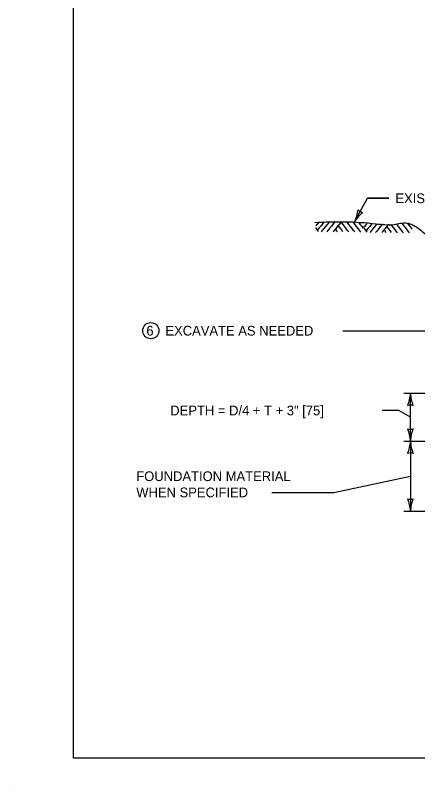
# Model space of a CAD drawing. Extents: x 49991.4 to 50021, y 49987.6 to 50011.4.
# Drawn here: x 49999.024 to 50001.509, y 49987.599 to 49992.388 of the extents above; entities that cross this region are included whole.
import ezdxf

# ---------------------------------------------------------------- set-up
doc = ezdxf.new("R2010")
doc.units = 0
for name, color, linetype in [('Level 1', 7, 'Continuous'), ('Level 2', 7, 'Continuous'), ('Level 3', 7, 'Continuous')]:
    doc.layers.add(name, color=color, linetype=linetype)

msp = doc.modelspace()

# ---------------------------------------------------------------- linework, layer by layer
at = {"layer": 'Level 1'}
msp.add_line((49999.0245, 49987.5988), (49999.0245, 49987.5988), dxfattribs=at)
msp.add_lwpolyline([(49999.3835, 49998.9992), (50016.7501, 49998.9992), (50016.7501, 49987.7988), (49999.3835, 49987.7988)], close=True, dxfattribs=at)
for points in [[(50000.8978, 49991.0536), (50000.8918, 49991.0618), (50000.89, 49991.0614), (50000.8904, 49991.0629), (50000.8821, 49991.0736), (50000.8827, 49991.0757), (50000.8806, 49991.0759), (50000.8801, 49991.0766)], [(50000.8988, 49991.1098), (50000.8906, 49991.1002), (50000.8914, 49991.0986), (50000.8898, 49991.0986), (50000.8813, 49991.0881), (50000.8802, 49991.0882)], [(50000.932, 49991.1125), (50000.922, 49991.1009), (50000.9228, 49991.0993), (50000.9212, 49991.0993), (50000.9127, 49991.0888), (50000.9106, 49991.0889), (50000.9108, 49991.0868), (50000.902, 49991.0763), (50000.902, 49991.0742), (50000.9001, 49991.0736), (50000.8932, 49991.0649)], [(50000.9648, 49991.1137), (50000.9521, 49991.0989), (50000.9529, 49991.0973), (50000.9513, 49991.0973), (50000.9428, 49991.0869), (50000.9406, 49991.0869), (50000.9409, 49991.0849), (50000.9321, 49991.0743), (50000.9321, 49991.0722), (50000.9302, 49991.0716), (50000.9218, 49991.0611), (50000.9198, 49991.061), (50000.9202, 49991.059), (50000.9141, 49991.0519)], [(50000.9985, 49991.1131), (50000.9862, 49991.0986), (50000.9869, 49991.097), (50000.9853, 49991.0971), (50000.9768, 49991.0866), (50000.9747, 49991.0866), (50000.9749, 49991.0846), (50000.9661, 49991.074), (50000.9661, 49991.072), (50000.9642, 49991.0713), (50000.9559, 49991.0609), (50000.9539, 49991.0607), (50000.9542, 49991.0587), (50000.9482, 49991.0516)], [(50001.0388, 49991.1139), (50001.0261, 49991.0991), (50001.0268, 49991.0974), (50001.0252, 49991.0975), (50001.0167, 49991.087), (50001.0146, 49991.087), (50001.0148, 49991.085), (50001.0061, 49991.0744), (50001.006, 49991.0724), (50001.0041, 49991.0717), (50000.9958, 49991.0613), (50000.9937, 49991.0612), (50000.9941, 49991.0591), (50000.9881, 49991.052)], [(50001.0484, 49991.052), (50001.0389, 49991.0644), (50001.037, 49991.0649), (50001.0368, 49991.0668), (50001.0284, 49991.0774), (50001.0288, 49991.0793), (50001.0267, 49991.0794), (50001.0189, 49991.0899)], [(50001.0839, 49991.0504), (50001.0786, 49991.0577), (50001.0769, 49991.0573), (50001.0773, 49991.0588), (50001.069, 49991.0695), (50001.0695, 49991.0715), (50001.0675, 49991.0718), (50001.0591, 49991.0827), (50001.0572, 49991.0832), (50001.057, 49991.0852), (50001.0487, 49991.0957), (50001.049, 49991.0977), (50001.047, 49991.0978), (50001.0375, 49991.1104)], [(50001.1207, 49991.0505), (50001.1145, 49991.0588), (50001.1128, 49991.0584), (50001.1132, 49991.06), (50001.1049, 49991.0706), (50001.1054, 49991.0727), (50001.1034, 49991.0729), (50001.095, 49991.0839), (50001.0931, 49991.0844), (50001.0929, 49991.0863), (50001.0846, 49991.0969), (50001.0849, 49991.0989), (50001.0829, 49991.099), (50001.0725, 49991.1128)], [(50001.1596, 49991.0491), (50001.1534, 49991.0574), (50001.1517, 49991.057), (50001.1521, 49991.0585), (50001.1438, 49991.0692), (50001.1443, 49991.0713), (50001.1423, 49991.0715), (50001.134, 49991.0824), (50001.132, 49991.0829), (50001.1318, 49991.0849), (50001.1235, 49991.0954), (50001.1238, 49991.0974), (50001.1218, 49991.0975), (50001.1126, 49991.1098)], [(50001.1759, 49991.0718), (50001.1681, 49991.082), (50001.1662, 49991.0825), (50001.166, 49991.0845), (50001.1577, 49991.095), (50001.158, 49991.097), (50001.1559, 49991.0971), (50001.1482, 49991.1075)], [(50001.1787, 49991.0833), (50001.1776, 49991.0833), (50001.1778, 49991.0813), (50001.1746, 49991.0773)], [(50001.1983, 49991.1033), (50001.1915, 49991.0953), (50001.1923, 49991.0937), (50001.1906, 49991.0937), (50001.1822, 49991.0832), (50001.181, 49991.0833)], [(50001.2282, 49991.1022), (50001.2229, 49991.096), (50001.2237, 49991.0944), (50001.2221, 49991.0944), (50001.2136, 49991.0839), (50001.2114, 49991.084), (50001.2117, 49991.0819), (50001.2029, 49991.0714), (50001.2029, 49991.0693), (50001.201, 49991.0687), (50001.1941, 49991.06)], [(50001.2577, 49991.0995), (50001.253, 49991.094), (50001.2538, 49991.0924), (50001.2522, 49991.0924), (50001.2437, 49991.082), (50001.2415, 49991.082), (50001.2418, 49991.08), (50001.233, 49991.0694), (50001.233, 49991.0673), (50001.2311, 49991.0667), (50001.2227, 49991.0562), (50001.2207, 49991.0561), (50001.221, 49991.0541), (50001.215, 49991.047)], [(50001.2919, 49991.0994), (50001.287, 49991.0937), (50001.2878, 49991.0921), (50001.2862, 49991.0922), (50001.2777, 49991.0817), (50001.2756, 49991.0817), (50001.2758, 49991.0797), (50001.267, 49991.0691), (50001.267, 49991.0671), (50001.2651, 49991.0664), (50001.2568, 49991.056), (50001.2547, 49991.0559), (50001.2551, 49991.0538), (50001.2491, 49991.0467)], [(50001.3299, 49991.0976), (50001.327, 49991.0942), (50001.3277, 49991.0925), (50001.3261, 49991.0926), (50001.3176, 49991.0821), (50001.3155, 49991.0821), (50001.3157, 49991.0801), (50001.3069, 49991.0695), (50001.3069, 49991.0675), (50001.305, 49991.0668), (50001.2967, 49991.0564), (50001.2946, 49991.0563), (50001.295, 49991.0542), (50001.289, 49991.0471)], [(50001.3493, 49991.0471), (50001.3398, 49991.0595), (50001.3379, 49991.06), (50001.3376, 49991.0619), (50001.3293, 49991.0725), (50001.3297, 49991.0745), (50001.3276, 49991.0745), (50001.3202, 49991.0845)], [(50001.3848, 49991.0455), (50001.3795, 49991.0528), (50001.3778, 49991.0524), (50001.3782, 49991.0539), (50001.3699, 49991.0646), (50001.3704, 49991.0667), (50001.3684, 49991.0669), (50001.36, 49991.0778), (50001.3581, 49991.0783), (50001.3579, 49991.0803), (50001.3496, 49991.0908), (50001.3499, 49991.0928), (50001.3478, 49991.0929), (50001.3447, 49991.0971)], [(50001.4215, 49991.0456), (50001.4154, 49991.0539), (50001.4137, 49991.0535), (50001.4141, 49991.0551), (50001.4058, 49991.0657), (50001.4063, 49991.0678), (50001.4043, 49991.068), (50001.3959, 49991.079), (50001.394, 49991.0795), (50001.3938, 49991.0814), (50001.3855, 49991.092), (50001.3858, 49991.094), (50001.3837, 49991.0941), (50001.3812, 49991.0975)], [(50001.4604, 49991.0442), (50001.4543, 49991.0525), (50001.4526, 49991.0521), (50001.453, 49991.0536), (50001.4447, 49991.0643), (50001.4452, 49991.0664), (50001.4432, 49991.0666), (50001.4348, 49991.0775), (50001.4329, 49991.078), (50001.4327, 49991.08), (50001.4244, 49991.0905), (50001.4247, 49991.0925), (50001.4227, 49991.0926), (50001.416, 49991.1015)], [(50001.4768, 49991.0669), (50001.469, 49991.0771), (50001.467, 49991.0776), (50001.4669, 49991.0796), (50001.4586, 49991.0901), (50001.4589, 49991.0921), (50001.4568, 49991.0922), (50001.4471, 49991.1052)], [(50001.0151, 49991.052), (50001.0092, 49991.0595), (50001.0096, 49991.0615), (50001.0075, 49991.0616), (50001.0018, 49991.0692)], [(50001.1987, 49991.0487), (50001.1927, 49991.0569), (50001.1909, 49991.0565), (50001.1913, 49991.058), (50001.183, 49991.0687), (50001.1836, 49991.0708), (50001.1815, 49991.071), (50001.181, 49991.0717)], [(50001.316, 49991.0471), (50001.3101, 49991.0546), (50001.3104, 49991.0566), (50001.3084, 49991.0567), (50001.3027, 49991.0643)]]:
    msp.add_lwpolyline(points, dxfattribs=at)
msp.add_spline([(50000.8753, 49991.1093), (50001.0614, 49991.1135), (50001.2517, 49991.1009), (50001.3638, 49991.0966), (50001.4442, 49991.1051), (50001.4781, 49991.0945), (50001.5454, 49991.0476), (50001.6157, 49990.9968)], degree=3, dxfattribs=at)
at = {"layer": 'Level 2'}
msp.add_circle((49999.861, 49990.44), 0.05, dxfattribs=at)
at = {"layer": 'Level 3'}
for p, q in [((50001.1192, 49991.1121), (50001.2003, 49991.2583)), ((50001.3325, 49991.2583), (50001.2003, 49991.2583)), ((50001.2003, 49991.2583), (50001.3325, 49991.2583)), ((50001.0483, 49990.44), (50002.0012, 49990.44)), ((50001.4254, 49990.0533), (50002.2929, 49990.0533)), ((50001.4654, 49989.7579), (50001.4654, 49990.0533)), ((50001.3944, 49989.9471), (50001.2905, 49989.9471)), ((50001.4654, 49989.9056), (50001.3944, 49989.9471)), ((50001.4254, 49989.7579), (50002.2924, 49989.7579)), ((50001.4654, 49989.7579), (50001.4654, 49989.3251)), ((50000.9914, 49989.4409), (50001.4654, 49989.5415)), ((50000.6083, 49989.4409), (50000.9914, 49989.4409)), ((50001.4254, 49989.3253), (50002.2929, 49989.3253))]:
    msp.add_line(p, q, dxfattribs=at)
for centre, radius, start, end in [((50000.9206, 49991.2118), 0.2223, 333.3425, 353.526), ((50001.3172, 49990.9891), 0.233, 128.9048, 148.1547), ((50001.1814, 49991.2242), 0.0548, 223.1208, 258.8432), ((50001.2433, 49990.0625), 0.2223, 337.456, 357.6395), ((50001.6981, 49990.0648), 0.233, 182.8273, 202.0772), ((50001.4654, 49989.9251), 0.0548, 72.1388, 107.8612), ((50001.4654, 49989.8861), 0.0548, 252.1388, 287.8612), ((50001.2327, 49989.7464), 0.233, 2.8273, 22.0772), ((50001.6875, 49989.7487), 0.2223, 157.456, 177.6395), ((50001.2433, 49989.767), 0.2223, 337.456, 357.6395), ((50001.6981, 49989.7694), 0.233, 182.8273, 202.0772), ((50001.4654, 49989.6297), 0.0548, 72.1388, 107.8612), ((50001.4654, 49989.4535), 0.0548, 252.1388, 287.8612), ((50001.2327, 49989.3138), 0.233, 2.8273, 22.0772), ((50001.6875, 49989.3162), 0.2223, 157.456, 177.6395)]:
    msp.add_arc(centre, radius, start, end, dxfattribs=at)

# ---------------------------------------------------------------- texts
at = {"layer": 'Level 2'}
for s, p in [('EXISTING GROUND', (50001.3725, 49991.2283)), ('6', (49999.8333, 49990.41)), ('EXCAVATE AS NEEDED', (49999.951, 49990.41)), ('DEPTH = D/4 + T + 3" [75]', (49999.981, 49989.9171)), ('FOUNDATION MATERIAL', (49999.771, 49989.5109)), ('WHEN SPECIFIED', (49999.771, 49989.4109))]:
    msp.add_text(s, height=0.06, dxfattribs=at).set_placement(p)

doc.saveas('drawing.dxf')
